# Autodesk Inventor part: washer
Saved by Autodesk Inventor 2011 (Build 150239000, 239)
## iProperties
Created: 2011-01
Part Number: washer
Document SubType Name: Modeling
Designer: dfranz
Density: 1 g/cm^3
Author: dfranz
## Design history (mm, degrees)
feature "Base1"
node "washer"
